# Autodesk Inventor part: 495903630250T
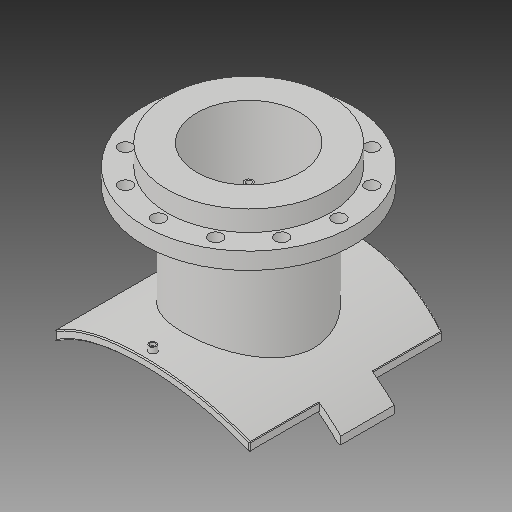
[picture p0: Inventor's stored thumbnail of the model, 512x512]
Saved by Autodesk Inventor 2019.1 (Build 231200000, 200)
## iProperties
Created: 2017-10
Part Number: 495903630250T
Material: Generic
Description: PLASSON FLANGED BRANCH SADDLE 500-630X250
Document SubType Name: Modeling
Designer: KIM
Mass: 2339.99 g
Surface Area: 3251.55 cm^2
Volume: 2339.99 cm^3
Density: 1 g/cm^3
Appearance: Default
Author: KIM
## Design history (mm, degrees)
derived "495904_495903.ipt"
feature "Solid1::495904_495903.ipt"
feature "Solid2::495904_495903.ipt"
tag "TaggingFeature1"
body "Solid1"
other parameters: "d1" = 15, "d2" = 382.5, "d4" = 0, "d6" = 105, "d7" = 0, "d12" = 340.6, "d13" = 14, "d14" = 189, "d16" = 5 deg, "d18" = 4, "d19" = 14, "d20" = 0, "d21" = 3, "d22" = 0, "d23" = 605, "d36" = 189, "d38" = 0, "d39" = 2, "d41" = 204, "d46" = 256, "d47" = 16, "d48" = 10.4, "d49" = 192.5, "d51" = 642.6, "d53" = 0, "d54" = 26, "d55" = 177.5, "d57" = 0, "d59" = 360 deg, "d61" = 33, "d63" = 0, "d66" = 275, "d67" = 15, "d68" = 137.5, "d70" = 0, "d71" = 2, "d72" = 425, "B_" = 425, "H_" = 275, "x_" = 15, "D_" = 16, "DN_" = 204, "t_" = 33, "s_" = 26, "Dp_" = 355
